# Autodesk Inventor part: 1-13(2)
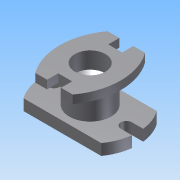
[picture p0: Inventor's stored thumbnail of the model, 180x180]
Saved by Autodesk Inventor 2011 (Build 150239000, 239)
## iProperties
Created: 2014-02
Part Number: 1-13(2)
Document SubType Name: Modeling
Designer: Administrator
Density: 1 g/cm^3
Author: Administrator
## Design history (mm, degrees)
sketch "草图1"
  geometry: L1 (-13.965, -10)-(13.965, -10); L2 (-13, 2)-(-17.06, 2); L3 (-13, -2)-(-17.06, -2); L4 (13, 2)-(17.06, 2); L5 (13, -2)-(17.06, -2); L6 (0, 14.568)-(0, -13.129); L7 (0, 0)-(36.151, 0); L8 (-13.965, 10)-(13.965, 10); A1 r 2 centre (-13, 0) between (-13, -2) and (-13, 2); A2 r 2 centre (13, 0) between (13, 2) and (13, -2); A3 r 17.176 centre (0, 0) between (-13.965, 10) and (-17.06, 2); A4 r 17.176 centre (0, 0) between (-17.06, -2) and (-13.965, -10); A5 r 17.176 centre (0, 0) between (13.965, -10) and (17.06, -2); A6 r 17.176 centre (0, 0) between (17.06, 2) and (13.965, 10); 3 further points
  constraints: 16 end point, 12 point on circle, 6 centre point, 4 parallel, 4 tangent, 2 perpendicular, 1 coincident, 1 vertical alignment, 1 other
  dimensions: "d13" = 26 distance of A2.centre A1.centre; "d15" = 10 distance from line of L1 point (0, 0)
extrude "拉伸1" new body sketch "草图1" distance "d0" = 4; taper "d1" = 0 deg
sketch "草图2"
  geometry: C1 r 7.5 at (0, 0); 1 further point
  constraints: 1 centre point, 1 coincident
  dimensions: "d16" = 15 diameter of C1
extrude "拉伸2" join sketch "草图2" distance "d2" = 10; taper "d3" = 0 deg
sketch "草图3"
  geometry: L1 (-2.5, -13)-(-2.5, -9); L2 (-2.5, -9)-(2.5, -9); L3 (2.5, -9)-(2.5, -13); L4 (-2.5, 13)-(-2.5, 9); L5 (-2.5, 9)-(2.5, 9); L6 (2.5, 9)-(2.5, 13); L7 (-6.735, 13)-(-2.5, 13); L8 (2.5, 13)-(6.735, 13); L9 (-6.735, -13)-(-2.5, -13); L10 (2.5, -13)-(6.735, -13); L11 (0, 0)-(23.022, 0); L12 (0, 0.766)-(0, 17.397); C1 r 7.5 at (0, 0) reference; A1 r 22 centre (11.013, 0) between (-6.735, 13) and (-6.735, -13); A2 r 22 centre (-11.013, 0) between (6.735, -13) and (6.735, 13); 2 further points
  constraints: 24 end point, 9 perpendicular, 6 parallel, 4 point on circle, 3 symmetric about line, 2 centre point, 2 horizontal, 2 midpoint, 2 vertical alignment, 4 other
  dimensions: "d17" = 18 distance between parallel lines of L5 L2; "d18" = 5 distance between parallel lines of L6 L4; "d19" = 5 distance between parallel lines of L3 L1; "d20" = 26 distance between parallel lines of L9 L7; "d22" = 22 radius of A1
extrude "拉伸6" join sketch "草图3" distance "d28" = 3; taper "d29" = 0 deg
sketch "草图7"
  geometry: C1 r 7.5 at (0, 0) reference
extrude "拉伸7" join sketch "草图7" distance "d30" = 3; taper "d31" = 0 deg
hole "Hole1" diameter "d34" = 11; stored, may be unused: countersink angle "d38" = 90 deg, drill point angle "d40" = 120 deg; dims "d32" = 10, "d33" = 10, "d35" = 6, "d36" = 4, "d37" = 2, "d39" = 6
hole "Hole2" diameter "d43" = 8; stored, may be unused: countersink angle "d47" = 90 deg, drill point angle "d49" = 120 deg; dims "d41" = 10, "d42" = 10, "d44" = 6, "d45" = 4, "d46" = 2, "d48" = 6
node "实体1"
